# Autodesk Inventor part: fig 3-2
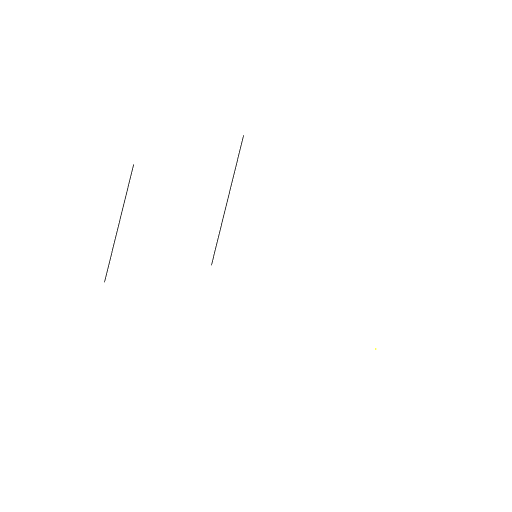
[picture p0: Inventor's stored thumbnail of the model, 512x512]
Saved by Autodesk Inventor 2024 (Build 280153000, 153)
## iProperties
Created: 2011-07
Part Number: fig 3-2
Material: Generic
Document SubType Name: Modeling
Designer: CadCim
Density: 1 g/cm^3
Appearance: Default
Author: CadCim
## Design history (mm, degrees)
sketch "Sketch1"
  geometry: L1 (-29, 4)-(-20, -8); L2 (-16, -0.965)-(-25.943, 12.292); 1 further point
  constraints: 4 end point, 1 parallel, 1 other
